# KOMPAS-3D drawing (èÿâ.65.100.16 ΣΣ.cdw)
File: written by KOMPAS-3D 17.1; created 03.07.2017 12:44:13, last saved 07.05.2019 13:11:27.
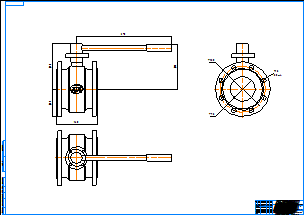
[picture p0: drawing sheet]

Sheet 1: A0, landscape

Title block, sheet 1: name: КШГ.65.100.16 фф; material: Внимание! Данный продукт является объектом авторского права ООО «Торговый Дом АДЛ». / Запрещается изменение, копирование, распространение / (в том числе путем копирования на другие сайты и ресурсы в Интернете) / или любое иное использование информации и объектов без предварительного / согласия правообладателя (ООО «Торговый Дом АДЛ»).; sheets: 1; organisation: ООО "Торговый дом АДЛ"; sheet format: A0; stored path: C:\Users\kka\KOMPAS_Work\!Trash\СС02 СС03 ФФ Смотровые стекла\СС01.cdw

Views: Спереди 1, Проекционный вид 2, Проекционный вид 3
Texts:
  Klimkovich
  ADL
Dimensions and other numbers on the sheet: 370; 175; 160; 107; 178; 180; 98; 18; 8 Отв.; 1:1; 1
